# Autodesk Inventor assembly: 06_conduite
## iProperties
Shininess: 41.0
Length Units: 11269
Angle Units: 11279
Time Units: 11290
Mass Units: 11283
Length Display Precision: 3
Angle Display Precision: 2
Compacted: True
Created: 2002-11
Part Number: 06_conduite
Document SubType Name: Assemblage
Designer: FIEVET
Density: 0.0
Volumn: 0.0
Area: 0.0
PropertySet Name: Model Information
Control State: 0
Master: False
Checked Out: False
Author: FIEVET
